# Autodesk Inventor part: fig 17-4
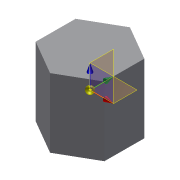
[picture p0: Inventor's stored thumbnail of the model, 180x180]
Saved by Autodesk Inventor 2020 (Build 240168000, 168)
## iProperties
Created: 2008-06
Part Number: fig 17-4
Document SubType Name: Modeling
Designer: CADCIM
Mass: 866.025 g
Surface Area: 519.615 cm^2
Volume: 866.025 cm^3
Density: 1 g/cm^3
Material: Generic
Appearance: Default
Author: CADCIM
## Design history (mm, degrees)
sketch "Sketch1"
  geometry: L1 (0.184, 57.735)-(50.092, 28.708); L2 (50.092, 28.708)-(49.908, -29.027); L3 (49.908, -29.027)-(-0.184, -57.735); L4 (-0.184, -57.735)-(-50.092, -28.708); L5 (-50.092, -28.708)-(-49.908, 29.027); L6 (-49.908, 29.027)-(0.184, 57.735); 1 further point
  constraints: 12 end point, 13 other
  dimensions: "d0" = 100 distance between parallel lines of L2 L5
extrude "Extrusion1" new body sketch "Sketch1" distance "d1" = 100; taper "d2" = 0 deg
body "Solid1"
